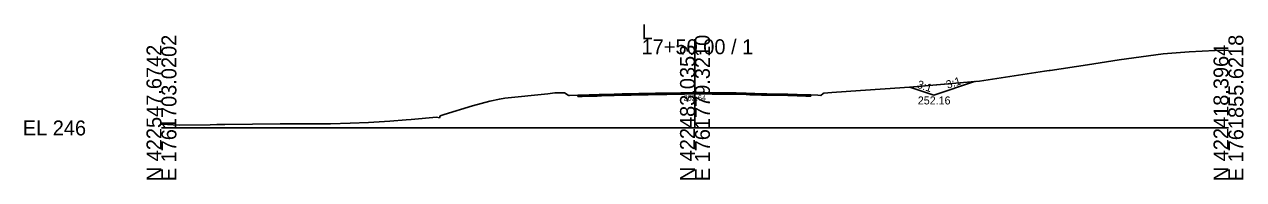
# Model space of a CAD drawing. Extents: x -26 to 3203, y -11010 to 4024.
# Drawn here: x -25.7 to 202.8, y -9009.7 to -8980.6 of the extents above; entities that cross this region are included whole.
import ezdxf

# ---------------------------------------------------------------- set-up
doc = ezdxf.new("R2010")
doc.units = 0
for name, color, linetype in [('Default', 7, 'Continuous'), ('Exist Cross Section Cell', 7, 'Continuous'), ('Exist XS Center Line Elevation Label', 7, 'Continuous'), ('Exist XS Ground Line', 7, 'Continuous'), ('Prop CMT Ditch DDE', 7, 'Continuous'), ('Prop CMT Pvmt Course 1', 7, 'Continuous'), ('Prop XS Ditch Standard Text', 7, 'Continuous'), ('Prop XS Side Slope Text', 7, 'Continuous'), ('Scratch_Level_0', 7, 'Continuous')]:
    doc.layers.add(name, color=color, linetype=linetype)

msp = doc.modelspace()

# ---------------------------------------------------------------- linework, layer by layer
at = {"layer": 'Exist Cross Section Cell'}
for p, q in [((100, -9000), (100, -8983.37)), ((0, -9000), (100, -9000)), ((100, -9000), (200, -9000))]:
    msp.add_line(p, q, dxfattribs=at)
at = {"layer": 'Exist XS Ground Line'}
msp.add_lwpolyline([(0, -8999.28), (3.3, -8999.46), (9.15, -8999.42), (10.4, -8999.37), (11.87, -8999.35), (22.25, -8999.24), (27.34, -8999.2), (31.68, -8999.2), (35.36, -8999.11), (38.78, -8998.99), (42.81, -8998.71), (45.87, -8998.5), (46.78, -8998.42), (51.55, -8997.99), (52.1, -8998.08), (52.25, -8997.73), (52.97, -8997.49), (58.28, -8995.88), (61.58, -8994.98), (63.36, -8994.57), (64.37, -8994.41), (72.41, -8993.6), (73.75, -8993.43), (74.44, -8993.4), (75.54, -8993.42), (76.24, -8993.86), (76.29, -8993.89), (76.5, -8993.89), (78.05, -8993.85), (78.57, -8993.84), (78.61, -8993.84), (78.85, -8993.83), (80.2, -8993.79), (81.64, -8993.76), (82.06, -8993.75), (82.5, -8993.74), (84.85, -8993.66), (86.37, -8993.62), (88.03, -8993.59), (89.45, -8993.55), (89.89, -8993.54), (90.57, -8993.52), (91.23, -8993.51), (92.6, -8993.49), (94.07, -8993.46), (94.73, -8993.45), (97.34, -8993.4), (97.82, -8993.39), (97.94, -8993.39), (98.04, -8993.39), (100.09, -8993.36), (100.31, -8993.36), (101.02, -8993.34), (101.86, -8993.35), (103.24, -8993.38), (104.51, -8993.39), (105.09, -8993.4), (105.74, -8993.4), (107.73, -8993.43), (109.59, -8993.49), (110.29, -8993.51), (110.93, -8993.52), (111.2, -8993.53), (112.47, -8993.57), (113.48, -8993.6), (114.37, -8993.63), (117.38, -8993.69), (117.4, -8993.69), (119.15, -8993.73), (120.79, -8993.78), (120.96, -8993.79), (121.71, -8993.81), (123.03, -8993.87), (123.58, -8993.89), (124.04, -8993.55), (124.16, -8993.46), (125.66, -8993.35), (131.02, -8992.96), (135.64, -8992.67), (140.21, -8992.34), (151.11, -8991.43), (153.31, -8991.22), (165.54, -8989.37), (166.42, -8989.24), (166.58, -8989.21), (173.59, -8988.13), (179.53, -8987.25), (187.78, -8986.11), (192.63, -8985.75), (197.52, -8985.49), (200, -8985.41)], dxfattribs=at)
msp.add_lwpolyline([(0, -8999.28), (3.3, -8999.46), (9.15, -8999.42), (10.4, -8999.37), (11.87, -8999.35), (22.25, -8999.24), (27.34, -8999.2), (31.68, -8999.2), (35.36, -8999.11), (38.78, -8998.99), (42.81, -8998.71), (45.87, -8998.5), (46.78, -8998.42), (51.55, -8997.99), (52.1, -8998.08), (52.25, -8997.73), (52.97, -8997.49), (58.28, -8995.88), (61.58, -8994.98), (63.36, -8994.57), (64.37, -8994.41), (72.41, -8993.6), (73.75, -8993.43), (74.44, -8993.4), (75.54, -8993.42), (76.24, -8993.86), (76.29, -8993.89), (76.5, -8993.89), (78.05, -8993.85), (78.57, -8993.84), (78.61, -8993.84), (78.85, -8993.83), (80.2, -8993.79), (81.64, -8993.76), (82.06, -8993.75), (82.5, -8993.74), (84.85, -8993.66), (86.37, -8993.62), (88.03, -8993.59), (89.45, -8993.55), (89.89, -8993.54), (90.57, -8993.52), (91.23, -8993.51), (92.6, -8993.49), (94.07, -8993.46), (94.73, -8993.45), (97.34, -8993.4), (97.82, -8993.39), (97.94, -8993.39), (98.04, -8993.39), (100.09, -8993.36), (100.31, -8993.36), (101.02, -8993.34), (101.86, -8993.35), (103.24, -8993.38), (104.51, -8993.39), (105.09, -8993.4), (105.74, -8993.4), (107.73, -8993.43), (109.59, -8993.49), (110.29, -8993.51), (110.93, -8993.52), (111.2, -8993.53), (112.47, -8993.57), (113.48, -8993.6), (114.37, -8993.63), (117.38, -8993.69), (117.4, -8993.69), (119.15, -8993.73), (120.79, -8993.78), (120.96, -8993.79), (121.71, -8993.81), (123.03, -8993.87), (123.58, -8993.89), (124.04, -8993.55), (124.16, -8993.46), (125.66, -8993.35), (131.02, -8992.96), (135.64, -8992.67), (140.21, -8992.34), (151.11, -8991.43), (153.31, -8991.22), (165.54, -8989.37), (166.42, -8989.24), (166.58, -8989.21), (173.59, -8988.13), (179.53, -8987.25), (187.78, -8986.11), (192.63, -8985.75), (197.52, -8985.49), (200, -8985.41)], dxfattribs=at)
msp.add_lwpolyline([(0, -8999.28), (3.3, -8999.46), (9.15, -8999.42), (10.4, -8999.37), (11.87, -8999.35), (22.25, -8999.24), (27.34, -8999.2), (31.68, -8999.2), (35.36, -8999.11), (38.78, -8998.99), (42.81, -8998.71), (45.87, -8998.5), (46.78, -8998.42), (51.55, -8997.99), (52.1, -8998.08), (52.25, -8997.73), (52.97, -8997.49), (58.28, -8995.88), (61.58, -8994.98), (63.36, -8994.57), (64.37, -8994.41), (72.41, -8993.6), (73.75, -8993.43), (74.44, -8993.4), (75.54, -8993.42), (76.24, -8993.86), (76.29, -8993.89), (76.5, -8993.89), (78.05, -8993.85), (78.57, -8993.84), (78.61, -8993.84), (78.85, -8993.83), (80.2, -8993.79), (81.64, -8993.76), (82.06, -8993.75), (82.5, -8993.74), (84.85, -8993.66), (86.37, -8993.62), (88.03, -8993.59), (89.45, -8993.55), (89.89, -8993.54), (90.57, -8993.52), (91.23, -8993.51), (92.6, -8993.49), (94.07, -8993.46), (94.73, -8993.45), (97.34, -8993.4), (97.82, -8993.39), (97.94, -8993.39), (98.04, -8993.39), (100.09, -8993.36), (100.31, -8993.36), (101.02, -8993.34), (101.86, -8993.35), (103.24, -8993.38), (104.51, -8993.39), (105.09, -8993.4), (105.74, -8993.4), (107.73, -8993.43), (109.59, -8993.49), (110.29, -8993.51), (110.93, -8993.52), (111.2, -8993.53), (112.47, -8993.57), (113.48, -8993.6), (114.37, -8993.63), (117.38, -8993.69), (117.4, -8993.69), (119.15, -8993.73), (120.79, -8993.78), (120.96, -8993.79), (121.71, -8993.81), (123.03, -8993.87), (123.58, -8993.89), (124.04, -8993.55), (124.16, -8993.46), (125.66, -8993.35), (131.02, -8992.96), (135.64, -8992.67), (140.21, -8992.34), (151.11, -8991.43), (153.31, -8991.22), (165.54, -8989.37), (166.42, -8989.24), (166.58, -8989.21), (173.59, -8988.13), (179.53, -8987.25), (187.78, -8986.11), (192.63, -8985.75), (197.52, -8985.49), (200, -8985.41)], dxfattribs=at)
msp.add_lwpolyline([(0, -8999.28), (3.3, -8999.46), (9.15, -8999.42), (10.4, -8999.37), (11.87, -8999.35), (22.25, -8999.24), (27.34, -8999.2), (31.68, -8999.2), (35.36, -8999.11), (38.78, -8998.99), (42.81, -8998.71), (45.87, -8998.5), (46.78, -8998.42), (51.55, -8997.99), (52.1, -8998.08), (52.25, -8997.73), (52.97, -8997.49), (58.28, -8995.88), (61.58, -8994.98), (63.36, -8994.57), (64.37, -8994.41), (72.41, -8993.6), (73.75, -8993.43), (74.44, -8993.4), (75.54, -8993.42), (76.24, -8993.86), (76.29, -8993.89), (76.5, -8993.89), (78.05, -8993.85), (78.57, -8993.84), (78.61, -8993.84), (78.85, -8993.83), (80.2, -8993.79), (81.64, -8993.76), (82.06, -8993.75), (82.5, -8993.74), (84.85, -8993.66), (86.37, -8993.62), (88.03, -8993.59), (89.45, -8993.55), (89.89, -8993.54), (90.57, -8993.52), (91.23, -8993.51), (92.6, -8993.49), (94.07, -8993.46), (94.73, -8993.45), (97.34, -8993.4), (97.82, -8993.39), (97.94, -8993.39), (98.04, -8993.39), (100.09, -8993.36), (100.31, -8993.36), (101.02, -8993.34), (101.86, -8993.35), (103.24, -8993.38), (104.51, -8993.39), (105.09, -8993.4), (105.74, -8993.4), (107.73, -8993.43), (109.59, -8993.49), (110.29, -8993.51), (110.93, -8993.52), (111.2, -8993.53), (112.47, -8993.57), (113.48, -8993.6), (114.37, -8993.63), (117.38, -8993.69), (117.4, -8993.69), (119.15, -8993.73), (120.79, -8993.78), (120.96, -8993.79), (121.71, -8993.81), (123.03, -8993.87), (123.58, -8993.89), (124.04, -8993.55), (124.16, -8993.46), (125.66, -8993.35), (131.02, -8992.96), (135.64, -8992.67), (140.21, -8992.34), (151.11, -8991.43), (153.31, -8991.22), (165.54, -8989.37), (166.42, -8989.24), (166.58, -8989.21), (173.59, -8988.13), (179.53, -8987.25), (187.78, -8986.11), (192.63, -8985.75), (197.52, -8985.49), (200, -8985.41)], dxfattribs=at)
msp.add_lwpolyline([(0, -8999.28), (3.3, -8999.46), (9.15, -8999.42), (10.4, -8999.37), (11.87, -8999.35), (22.25, -8999.24), (27.34, -8999.2), (31.68, -8999.2), (35.36, -8999.11), (38.78, -8998.99), (42.81, -8998.71), (45.87, -8998.5), (46.78, -8998.42), (51.55, -8997.99), (52.1, -8998.08), (52.25, -8997.73), (52.97, -8997.49), (58.28, -8995.88), (61.58, -8994.98), (63.36, -8994.57), (64.37, -8994.41), (72.41, -8993.6), (73.75, -8993.43), (74.44, -8993.4), (75.54, -8993.42), (76.24, -8993.86), (76.29, -8993.89), (76.5, -8993.89), (78.05, -8993.85), (78.57, -8993.84), (78.61, -8993.84), (78.85, -8993.83), (80.2, -8993.79), (81.64, -8993.76), (82.06, -8993.75), (82.5, -8993.74), (84.85, -8993.66), (86.37, -8993.62), (88.03, -8993.59), (89.45, -8993.55), (89.89, -8993.54), (90.57, -8993.52), (91.23, -8993.51), (92.6, -8993.49), (94.07, -8993.46), (94.73, -8993.45), (97.34, -8993.4), (97.82, -8993.39), (97.94, -8993.39), (98.04, -8993.39), (100.09, -8993.36), (100.31, -8993.36), (101.02, -8993.34), (101.86, -8993.35), (103.24, -8993.38), (104.51, -8993.39), (105.09, -8993.4), (105.74, -8993.4), (107.73, -8993.43), (109.59, -8993.49), (110.29, -8993.51), (110.93, -8993.52), (111.2, -8993.53), (112.47, -8993.57), (113.48, -8993.6), (114.37, -8993.63), (117.38, -8993.69), (117.4, -8993.69), (119.15, -8993.73), (120.79, -8993.78), (120.96, -8993.79), (121.71, -8993.81), (123.03, -8993.87), (123.58, -8993.89), (124.04, -8993.55), (124.16, -8993.46), (125.66, -8993.35), (131.02, -8992.96), (135.64, -8992.67), (140.21, -8992.34), (151.11, -8991.43), (153.31, -8991.22), (165.54, -8989.37), (166.42, -8989.24), (166.58, -8989.21), (173.59, -8988.13), (179.53, -8987.25), (187.78, -8986.11), (192.63, -8985.75), (197.52, -8985.49), (200, -8985.41)], dxfattribs=at)
at = {"layer": 'Prop CMT Ditch DDE'}
msp.add_lwpolyline([(140.29, -8992.34), (144.79, -8993.84), (152.38, -8991.31)], dxfattribs=at)
at = {"layer": 'Prop CMT Pvmt Course 1'}
for points in [[(78.05, -8993.85), (78.57, -8993.84), (78.61, -8993.84), (78.85, -8993.83), (80.2, -8993.79), (81.64, -8993.76), (82.06, -8993.75), (82.5, -8993.74), (84.85, -8993.66), (86.37, -8993.62), (88.03, -8993.59), (89.45, -8993.55), (89.89, -8993.54), (90.57, -8993.52), (91.23, -8993.51), (92.6, -8993.49), (94.07, -8993.46), (94.73, -8993.45), (97.34, -8993.4), (97.82, -8993.39), (97.94, -8993.39), (98.04, -8993.39), (100, -8993.36)], [(100, -8993.61), (98.04, -8993.64), (97.94, -8993.64), (97.82, -8993.64), (97.34, -8993.65), (94.73, -8993.7), (94.07, -8993.71), (92.6, -8993.74), (91.23, -8993.76), (90.57, -8993.77), (89.89, -8993.79), (89.45, -8993.8), (88.03, -8993.84), (86.37, -8993.87), (84.85, -8993.91), (82.5, -8993.99), (82.06, -8994), (81.64, -8994.01), (80.2, -8994.04), (78.85, -8994.08), (78.61, -8994.09), (78.57, -8994.09), (78.05, -8994.1)], [(78.05, -8994.1), (78.05, -8993.85)], [(100, -8993.36), (100.09, -8993.36), (100.31, -8993.36), (101.02, -8993.34), (101.86, -8993.35), (103.24, -8993.38), (104.51, -8993.39), (105.09, -8993.4), (105.74, -8993.4), (107.73, -8993.43), (109.59, -8993.49), (110.29, -8993.51), (110.93, -8993.52), (111.2, -8993.53), (112.47, -8993.57), (113.48, -8993.6), (114.37, -8993.63), (117.38, -8993.69), (117.4, -8993.69), (119.15, -8993.73), (120.79, -8993.78), (120.96, -8993.79), (121.71, -8993.81), (121.71, -8993.81)], [(100, -8993.36), (100, -8993.61)], [(100, -8993.61), (100, -8993.36)], [(121.71, -8994.06), (121.71, -8994.06), (120.96, -8994.04), (120.79, -8994.03), (119.15, -8993.98), (117.4, -8993.94), (117.38, -8993.94), (114.37, -8993.88), (113.48, -8993.85), (112.47, -8993.82), (111.2, -8993.78), (110.93, -8993.77), (110.29, -8993.76), (109.59, -8993.74), (107.73, -8993.68), (105.74, -8993.65), (105.09, -8993.65), (104.51, -8993.64), (103.24, -8993.63), (101.86, -8993.6), (101.02, -8993.59), (100.31, -8993.61), (100.09, -8993.61), (100, -8993.61)], [(121.71, -8993.81), (121.71, -8994.06)]]:
    msp.add_lwpolyline(points, dxfattribs=at)
at = {"layer": 'Scratch_Level_0'}
for p, q in [((151.11, -8991.43), (140.29, -8992.34)), ((152.38, -8991.31), (151.11, -8991.43))]:
    msp.add_line(p, q, dxfattribs=at)
msp.add_lwpolyline([(140.29, -8992.34), (144.79, -8993.84), (152.38, -8991.31)], dxfattribs=at)

# ---------------------------------------------------------------- texts
at = {"layer": 'Default'}
msp.add_text('-', height=0.0001, dxfattribs=at).set_placement((0, -9000))
at = {"layer": 'Exist Cross Section Cell'}
for s, p in [('L', (90, -8983.37)), ('17+50.00 / 1', (90, -8986.17)), ('EL 246', (-26, -9001.4))]:
    msp.add_text(s, height=2.8, dxfattribs=at).set_placement(p)
for s, p in [('E 1761703.0202', (2.8, -9010)), ('E 1761779.3210', (102.8, -9010)), ('E 1761855.6218', (202.8, -9010)), ('N 422547.6742', (0, -9010)), ('N 422483.0353', (100, -9010)), ('N 422418.3964', (200, -9010))]:
    msp.add_text(s, height=2.8, rotation=90, dxfattribs=at).set_placement(p)
at = {"layer": 'Exist XS Center Line Elevation Label'}
msp.add_text('252.64', height=1, dxfattribs=at).set_placement((97.86, -8994.86))
at = {"layer": 'Prop XS Ditch Standard Text'}
msp.add_text('252.16', height=1.5, dxfattribs=at).set_placement((141.77, -8995.59))
msp.add_text('252.16', height=1.5, dxfattribs=at).set_placement((141.77, -8995.59))
msp.add_text('252.16', height=1.5, dxfattribs=at).set_placement((141.77, -8995.59))
at = {"layer": 'Prop XS Side Slope Text'}
for rotation, p in [(341.5651, (141.51, -8992.43)), (18.4349, (147.36, -8992.66))]:
    msp.add_text('3:1', height=1.5, rotation=rotation, dxfattribs=at).set_placement(p)
at = {"layer": 'Scratch_Level_0'}
for s, p in [('RT_SS_Fill_Point', (140.17, -8992.35)), ('RT_DD_Boundary Out', (152.21, -8991.32)), ('Exterior Boundary', (152.22, -8991.32)), ('Exterior Boundary', (77.89, -8993.86)), ('LT_Res Edge', (77.95, -8993.86)), ('PV1_PGL', (99.95, -8993.37)), ('RT_Res_Edge', (121.61, -8993.82)), ('RT_DD_Base In', (144.68, -8993.85))]:
    msp.add_text(s, height=0.02, dxfattribs=at).set_placement(p)

doc.saveas('drawing.dxf')
